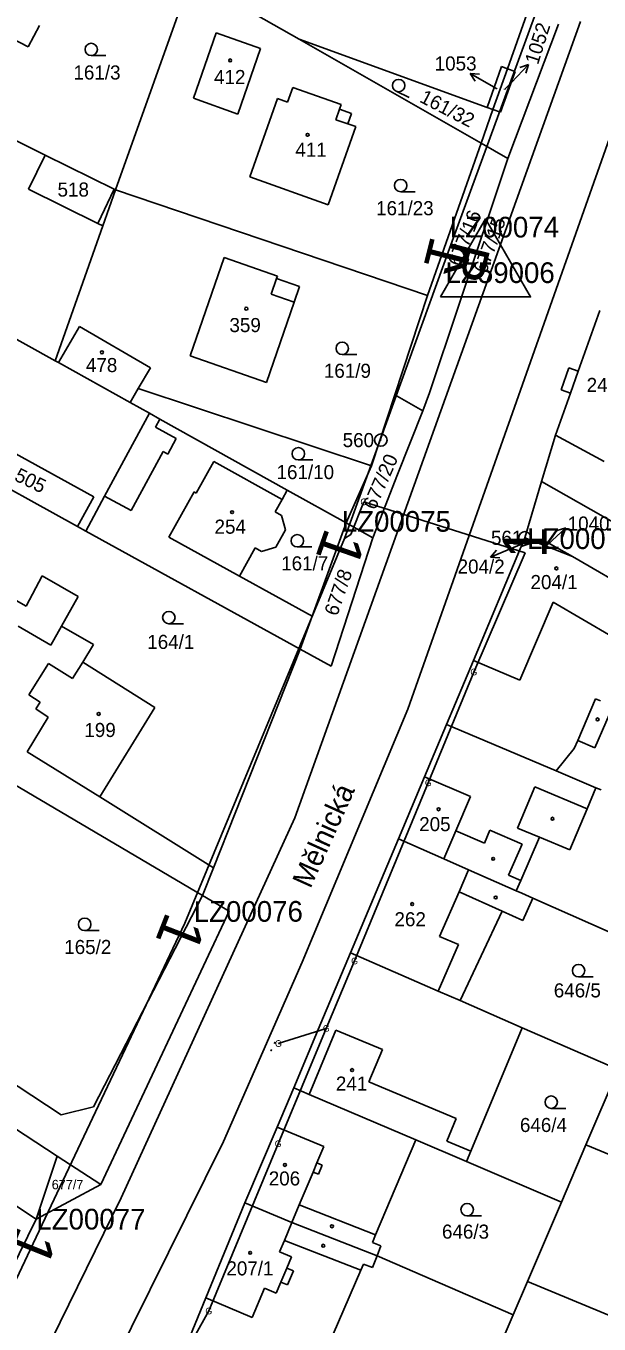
# Model space of a CAD drawing. Extents: x -738131 to -734179, y -1033447 to -1030078.
# Drawn here: x -736203.5 to -736134.3, y -1032598.8 to -1032442 of the extents above; entities that cross this region are included whole.
import ezdxf

# ---------------------------------------------------------------- set-up
doc = ezdxf.new("R2010")
doc.units = 0
for name, color, linetype in [('ftf_2010', 7, 'Continuous'), ('ftf_2050', 7, 'Continuous'), ('ftf_2240', 7, 'Continuous'), ('ftf_3010', 7, 'Continuous'), ('ftf_3010_ftf_3010_gtda_3015_gtda_3015_1', 7, 'Continuous'), ('ftf_3130', 7, 'Continuous'), ('ftf_3240', 7, 'Continuous'), ('ftf_3270', 7, 'Continuous'), ('ftf_3270_ftf_3270_gtda_3275_gtda_3275_1', 7, 'Continuous'), ('ftf_nu', 7, 'Continuous'), ('Vrstva 1', 7, 'Continuous'), ('Vrstva 2', 7, 'Continuous'), ('Vrstva 3', 7, 'Continuous'), ('Vrstva 4', 7, 'Continuous'), ('Vrstva 5', 7, 'Continuous'), ('Vrstva 7', 7, 'Continuous'), ('Vrstva 8', 7, 'Continuous')]:
    doc.layers.add(name, color=color, linetype=linetype)

msp = doc.modelspace()

# ---------------------------------------------------------------- linework, layer by layer
at = {"layer": 'ftf_2010'}
for points in [[(-736140.32, -1032436.02), (-736152.22, -1032468.46)], [(-736165.07, -1032503.95), (-736152.22, -1032468.46)], [(-736165.07, -1032503.95), (-736164.3, -1032503.44), (-736162.74, -1032499.51)], [(-736184.37, -1032550.41), (-736165.07, -1032503.95)], [(-736184.37, -1032550.41), (-736202.33, -1032588.35)], [(-736221.64, -1032629.17), (-736202.33, -1032588.35)]]:
    msp.add_lwpolyline(points, dxfattribs=at)
at = {"layer": 'ftf_2050'}
for points in [[(-736162.74, -1032499.51), (-736143.22, -1032505.69)], [(-736192.27, -1032616.69), (-736181.47, -1032597.25), (-736173.09, -1032577.05), (-736167.27, -1032563.11), (-736163.85, -1032554.97), (-736154.94, -1032533.45), (-736149.45, -1032520.07), (-736143.22, -1032505.69)], [(-736173.06, -1032564.94), (-736167.27, -1032563.11)]]:
    msp.add_lwpolyline(points, dxfattribs=at)
at = {"layer": 'ftf_2240'}
msp.add_lwpolyline([(-736153.46, -1032474.76), (-736142.58, -1032474.76), (-736148.02, -1032465.33)], close=True, dxfattribs=at)
at = {"layer": 'Vrstva 1'}
for points in [[(-736138.11, -1032426.67), (-736145.37, -1032447.19)], [(-736183.6, -1032436.18), (-736192.74, -1032461.81)], [(-736177.86, -1032439.46), (-736170.55, -1032443.63)], [(-736203.28, -1032444.56), (-736208.69, -1032441.76)], [(-736136.53, -1032441.5), (-736171.05, -1032537.69)], [(-736201.92, -1032441.96), (-736203.28, -1032444.56)], [(-736183.32, -1032450.77), (-736180.55, -1032442.88)], [(-736180.55, -1032442.88), (-736175.2, -1032444.76)], [(-736139.18, -1032441.8), (-736145.31, -1032458.03)], [(-736175.2, -1032444.76), (-736177.96, -1032452.67)], [(-736170.55, -1032443.63), (-736148.55, -1032456.18)], [(-736147.83, -1032451.86), (-736170.55, -1032443.63)], [(-736129.47, -1032445.45), (-736157.4, -1032524.54)], [(-736201.23, -1032457.62), (-736221.77, -1032447.35)], [(-736146.08, -1032446.94), (-736147.83, -1032451.86)], [(-736147.13, -1032452.11), (-736145.37, -1032447.19)], [(-736144.44, -1032447.52), (-736146.2, -1032452.44)], [(-736145.37, -1032447.19), (-736146.08, -1032446.94)], [(-736145.37, -1032447.19), (-736144.44, -1032447.52)], [(-736171.31, -1032449.45), (-736171.96, -1032451.25)], [(-736165.45, -1032451.52), (-736171.31, -1032449.45)], [(-736177.96, -1032452.67), (-736183.32, -1032450.77)], [(-736173.17, -1032450.81), (-736176.48, -1032460.24)], [(-736171.96, -1032451.25), (-736173.17, -1032450.81)], [(-736165.65, -1032452.1), (-736165.45, -1032451.52)], [(-736164.21, -1032452.61), (-736165.65, -1032452.1)], [(-736164.65, -1032453.86), (-736164.21, -1032452.61)], [(-736147.13, -1032452.11), (-736148.55, -1032456.18)], [(-736147.13, -1032452.11), (-736147.83, -1032451.86)], [(-736146.2, -1032452.44), (-736147.13, -1032452.11)], [(-736167.05, -1032463.62), (-736163.67, -1032454.18)], [(-736163.67, -1032454.18), (-736164.65, -1032453.86)], [(-736148.55, -1032456.18), (-736155.02, -1032474.6)], [(-736148.55, -1032456.18), (-736145.31, -1032458.03)], [(-736201.23, -1032457.62), (-736203.26, -1032461.74)], [(-736192.88, -1032461.74), (-736201.23, -1032457.62)], [(-736145.31, -1032458.03), (-736151.27, -1032475.87)], [(-736176.48, -1032460.24), (-736167.05, -1032463.62)], [(-736203.26, -1032461.74), (-736194.85, -1032465.88)], [(-736192.74, -1032461.81), (-736194.27, -1032466.16)], [(-736192.74, -1032461.81), (-736192.88, -1032461.74)], [(-736155.02, -1032474.6), (-736192.74, -1032461.81)], [(-736200.01, -1032482.48), (-736230.49, -1032465.51)], [(-736194.27, -1032466.16), (-736200.01, -1032482.48)], [(-736194.85, -1032465.88), (-736194.27, -1032466.16)], [(-736183.72, -1032481.89), (-736179.58, -1032470.01)], [(-736179.58, -1032470.01), (-736173.16, -1032472.25)], [(-736173.16, -1032472.25), (-736173.26, -1032472.53)], [(-736170.48, -1032473.49), (-736173.26, -1032472.53)], [(-736171.13, -1032475.38), (-736170.48, -1032473.49)], [(-736158.98, -1032486.59), (-736155.02, -1032474.6)], [(-736171.13, -1032475.38), (-736174.49, -1032485.11)], [(-736151.27, -1032475.87), (-736154.77, -1032486.36)], [(-736134.21, -1032476.39), (-736136.82, -1032483.74)], [(-736197.09, -1032478.34), (-736199.62, -1032482.7)], [(-736188.5, -1032483.33), (-736197.09, -1032478.34)], [(-736200.01, -1032482.48), (-736199.62, -1032482.7)], [(-736174.49, -1032485.11), (-736183.72, -1032481.89)], [(-736199.62, -1032482.7), (-736190.97, -1032487.52)], [(-736189.97, -1032485.82), (-736188.5, -1032483.33)], [(-736137.95, -1032483.34), (-736138.89, -1032485.98)], [(-736136.82, -1032483.74), (-736137.95, -1032483.34)], [(-736190.97, -1032487.52), (-736189.97, -1032485.82)], [(-736189.97, -1032485.82), (-736161.81, -1032495.17)], [(-736161.81, -1032495.17), (-736158.98, -1032486.59)], [(-736158.98, -1032486.59), (-736155.61, -1032488.51)], [(-736155.61, -1032488.51), (-736154.77, -1032486.36)], [(-736137.76, -1032486.38), (-736139.57, -1032491.47)], [(-736138.89, -1032485.98), (-736137.76, -1032486.38)], [(-736190.97, -1032487.52), (-736188.62, -1032488.82)], [(-736158.64, -1032496.22), (-736155.61, -1032488.51)], [(-736188.62, -1032488.82), (-736194.05, -1032498.84)], [(-736188.62, -1032488.82), (-736187.36, -1032489.53)], [(-736187.36, -1032489.53), (-736171.97, -1032498.1)], [(-736209.21, -1032491.28), (-736195.34, -1032498.92)], [(-736141.24, -1032497.07), (-736139.57, -1032491.47)], [(-736133.68, -1032494.64), (-736139.57, -1032491.47)], [(-736197.31, -1032502.49), (-736211.18, -1032494.85)], [(-736164.86, -1032502.06), (-736161.81, -1032495.17)], [(-736161.63, -1032503.86), (-736158.64, -1032496.22)], [(-736171.97, -1032498.1), (-736172.6, -1032499.23)], [(-736171.97, -1032498.1), (-736164.86, -1032502.06)], [(-736143.26, -1032503.85), (-736141.24, -1032497.07)], [(-736141.24, -1032497.07), (-736107.27, -1032516.33)], [(-736195.34, -1032498.92), (-736197.31, -1032502.49)], [(-736196.32, -1032503.04), (-736194.05, -1032498.84)], [(-736172.6, -1032499.23), (-736173.43, -1032500.71)], [(-736173.43, -1032500.71), (-736172.65, -1032501.15)], [(-736172.65, -1032501.15), (-736172.19, -1032502.89)], [(-736197.31, -1032502.49), (-736196.32, -1032503.04)], [(-736172.19, -1032502.89), (-736173.36, -1032504.99)], [(-736164.86, -1032502.06), (-736168.97, -1032513.32)], [(-736164.86, -1032502.06), (-736161.63, -1032503.86)], [(-736196.32, -1032503.04), (-736170.42, -1032517.31)], [(-736166.66, -1032519.38), (-736161.63, -1032503.86)], [(-736143.71, -1032504.91), (-736143.26, -1032503.85)], [(-736143.71, -1032504.91), (-736142.03, -1032504.34)], [(-736143.26, -1032503.85), (-736142.03, -1032504.34)], [(-736142.03, -1032504.34), (-736141.19, -1032504.05)], [(-736142.03, -1032504.34), (-736137.49, -1032506.13)], [(-736137.49, -1032506.13), (-736141.19, -1032504.05)], [(-736177.76, -1032508.47), (-736175.86, -1032505.07)], [(-736175.08, -1032505.51), (-736175.86, -1032505.07)], [(-736173.36, -1032504.99), (-736175.08, -1032505.51)], [(-736149.47, -1032518.66), (-736143.71, -1032504.91)], [(-736129.73, -1032510.63), (-736137.49, -1032506.13)], [(-736209.99, -1032508.46), (-736203.54, -1032512.11)], [(-736203.54, -1032512.11), (-736201.57, -1032508.46)], [(-736201.57, -1032508.46), (-736197.24, -1032510.94)], [(-736168.97, -1032513.32), (-736177.76, -1032508.47)], [(-736197.24, -1032510.94), (-736199.25, -1032514.54)], [(-736170.42, -1032517.31), (-736168.97, -1032513.32)], [(-736199.25, -1032514.54), (-736195.38, -1032516.74)], [(-736195.38, -1032516.74), (-736196.69, -1032518.87)], [(-736170.42, -1032517.31), (-736180.88, -1032543.74)], [(-736170.42, -1032517.31), (-736166.66, -1032519.38)], [(-736196.69, -1032518.87), (-736187.98, -1032524.34)], [(-736149.47, -1032518.66), (-736152.73, -1032526.39)], [(-736134.79, -1032529.22), (-736132.16, -1032523.12)], [(-736187.98, -1032524.34), (-736194.62, -1032535.14)], [(-736157.4, -1032524.54), (-736170.16, -1032555.11)], [(-736152.73, -1032526.39), (-736155.39, -1032532.73)], [(-736152.73, -1032526.39), (-736139.48, -1032532.01)], [(-736139.48, -1032532.01), (-736137.31, -1032529.32)], [(-736137.31, -1032529.32), (-736136.88, -1032528.32)], [(-736134.79, -1032529.22), (-736136.88, -1032528.32)], [(-736139.48, -1032532.01), (-736134.7, -1032534.04)], [(-736205.03, -1032533.62), (-736182.2, -1032547.07)], [(-736155.39, -1032532.73), (-736158.54, -1032540.21)], [(-736135.75, -1032536.58), (-736134.7, -1032534.04)], [(-736134.7, -1032534.04), (-736134.06, -1032534.31)], [(-736180.88, -1032543.74), (-736194.62, -1032535.14)], [(-736137.82, -1032541.56), (-736135.75, -1032536.58)], [(-736171.05, -1032537.69), (-736192.06, -1032583.58)], [(-736158.54, -1032540.21), (-736161.23, -1032546.62)], [(-736158.54, -1032540.21), (-736153.04, -1032542.64)], [(-736143.76, -1032545.25), (-736141.51, -1032540.02)], [(-736141.51, -1032540.02), (-736137.82, -1032541.56)], [(-736153.04, -1032542.64), (-736150.06, -1032543.96)], [(-736182.2, -1032547.07), (-736180.88, -1032543.74)], [(-736144.3, -1032546.5), (-736150.06, -1032543.96)], [(-736161.23, -1032546.62), (-736164.33, -1032553.99)], [(-736144.3, -1032546.5), (-736143.76, -1032545.25)], [(-736143.64, -1032546.79), (-736144.3, -1032546.5)], [(-736142.3, -1032547.39), (-736143.64, -1032546.79)], [(-736182.2, -1032547.07), (-736195.37, -1032572.58)], [(-736182.2, -1032547.07), (-736179, -1032548.95)], [(-736142.3, -1032547.39), (-736143.52, -1032550.09)], [(-736142.3, -1032547.39), (-736126.18, -1032554.51)], [(-736194.49, -1032581.99), (-736179, -1032548.95)], [(-736146.01, -1032548.97), (-736151.07, -1032559.76)], [(-736143.52, -1032550.09), (-736146.01, -1032548.97)], [(-736164.33, -1032553.99), (-736167.91, -1032562.5)], [(-736164.33, -1032553.99), (-736153.75, -1032558.6)], [(-736170.16, -1032555.11), (-736179.69, -1032576.78)], [(-736199.28, -1032573.57), (-736225.57, -1032556.27)], [(-736151.07, -1032559.76), (-736153.75, -1032558.6)], [(-736228.16, -1032559.94), (-736199.76, -1032578.54)], [(-736143.57, -1032563.03), (-736151.07, -1032559.76)], [(-736167.91, -1032562.5), (-736171.19, -1032570.3)], [(-736143.57, -1032563.03), (-736149.78, -1032577.96)], [(-736131.98, -1032568.07), (-736143.57, -1032563.03)], [(-736131.98, -1032568.07), (-736135.88, -1032577.19)], [(-736171.19, -1032570.3), (-736173.18, -1032575.05)], [(-736169.34, -1032571.09), (-736171.19, -1032570.3)], [(-736156.45, -1032576.59), (-736169.34, -1032571.09)], [(-736199.28, -1032573.57), (-736195.37, -1032572.58)], [(-736177.11, -1032584.18), (-736173.18, -1032575.05)], [(-736161.32, -1032588.03), (-736156.45, -1032576.59)], [(-736150.3, -1032579.21), (-736156.45, -1032576.59)], [(-736214.51, -1032578.06), (-736202.32, -1032586.14)], [(-736179.69, -1032576.78), (-736197.43, -1032612.62)], [(-736149.78, -1032577.96), (-736150.3, -1032579.21)], [(-736135.88, -1032577.19), (-736138.84, -1032584.1)], [(-736135.88, -1032577.19), (-736108.36, -1032588.58)], [(-736202.32, -1032586.14), (-736199.76, -1032578.54)], [(-736199.76, -1032578.54), (-736194.49, -1032581.99)], [(-736138.84, -1032584.1), (-736150.3, -1032579.21)], [(-736202.32, -1032586.14), (-736194.49, -1032581.99)], [(-736192.06, -1032583.58), (-736209.97, -1032620)], [(-736177.11, -1032584.18), (-736181.81, -1032595.67)], [(-736171.41, -1032586.56), (-736177.11, -1032584.18)], [(-736138.84, -1032584.1), (-736142.94, -1032593.68)], [(-736202.32, -1032586.14), (-736214.65, -1032611.21)], [(-736161.13, -1032590.58), (-736171.41, -1032586.56)], [(-736161.32, -1032588.03), (-736161.69, -1032588.96)], [(-736161.69, -1032588.96), (-736160.66, -1032589.37)], [(-736161.13, -1032590.58), (-736161.69, -1032592.01)], [(-736160.66, -1032589.37), (-736161.13, -1032590.58)], [(-736161.13, -1032590.58), (-736144.67, -1032597.7)], [(-736162.78, -1032591.58), (-736163.07, -1032592.33)], [(-736161.69, -1032592.01), (-736162.78, -1032591.58)], [(-736163.07, -1032592.33), (-736167.83, -1032603.32)], [(-736142.94, -1032593.68), (-736144.67, -1032597.7)], [(-736113.43, -1032605.92), (-736142.94, -1032593.68)], [(-736181.81, -1032595.67), (-736183.74, -1032600.39)], [(-736150.39, -1032611.09), (-736144.67, -1032597.7)]]:
    msp.add_lwpolyline(points, dxfattribs=at)
at = {"layer": 'Vrstva 3'}
for p, q in [((-736195.66, -1032445.61), (-736193.91, -1032445.61)), ((-736158.83, -1032449.91), (-736157.25, -1032450.66)), ((-736158.27, -1032462.06), (-736156.52, -1032462.06)), ((-736165.33, -1032481.72), (-736163.58, -1032481.72)), ((-736170.63, -1032494.45), (-736168.88, -1032494.45)), ((-736170.76, -1032504.96), (-736169.01, -1032504.96)), ((-736186.28, -1032514.24), (-736184.53, -1032514.24)), ((-736196.45, -1032551.3), (-736194.7, -1032551.3)), ((-736136.77, -1032556.89), (-736135.02, -1032556.89)), ((-736140.08, -1032572.77), (-736138.33, -1032572.77)), ((-736150.24, -1032585.76), (-736148.49, -1032585.76))]:
    msp.add_line(p, q, dxfattribs=at)
for centre in [(-736195.66, -1032444.86), (-736158.51, -1032449.23), (-736158.27, -1032461.31), (-736165.33, -1032480.97), (-736170.63, -1032493.7), (-736170.76, -1032504.21), (-736186.28, -1032513.49), (-736196.45, -1032550.55), (-736136.77, -1032556.14), (-736140.08, -1032572.02), (-736150.24, -1032585.01)]:
    msp.add_circle(centre, 0.75, dxfattribs=at)
at = {"layer": 'Vrstva 4'}
for points in [[(-736165.65, -1032452.1), (-736166.09, -1032453.35)], [(-736166.09, -1032453.35), (-736164.65, -1032453.86)], [(-736192.88, -1032461.74), (-736194.85, -1032465.88)], [(-736173.26, -1032472.53), (-736173.91, -1032474.41)], [(-736173.91, -1032474.41), (-736171.13, -1032475.38)], [(-736137.76, -1032486.38), (-736136.82, -1032483.74)], [(-736187.36, -1032489.53), (-736187.89, -1032490.51)], [(-736187.89, -1032490.51), (-736185.39, -1032491.86)], [(-736185.39, -1032491.86), (-736186.4, -1032493.74)], [(-736186.98, -1032493.43), (-736190.83, -1032500.57)], [(-736186.4, -1032493.74), (-736186.98, -1032493.43)], [(-736182.98, -1032498.47), (-736180.84, -1032494.64)], [(-736180.84, -1032494.64), (-736172.6, -1032499.23)], [(-736190.83, -1032500.57), (-736194.05, -1032498.84)], [(-736186.28, -1032503.77), (-736183.24, -1032498.32)], [(-736183.24, -1032498.32), (-736182.98, -1032498.47)], [(-736177.76, -1032508.47), (-736186.28, -1032503.77)], [(-736143.87, -1032521.05), (-736139.84, -1032511.63)], [(-736139.84, -1032511.63), (-736132.67, -1032515.81)], [(-736204.49, -1032514.53), (-736200.53, -1032516.83)], [(-736200.53, -1032516.83), (-736199.25, -1032514.54)], [(-736200.82, -1032519.02), (-736203.2, -1032522.81)], [(-736197.91, -1032520.85), (-736200.82, -1032519.02)], [(-736196.69, -1032518.87), (-736197.91, -1032520.85)], [(-736149.47, -1032518.66), (-736143.87, -1032521.05)], [(-736203.2, -1032522.81), (-736201.82, -1032523.71)], [(-736201.82, -1032523.71), (-736202.35, -1032524.53)], [(-736202.35, -1032524.53), (-736200.85, -1032525.54)], [(-736136.88, -1032528.32), (-736134.73, -1032523.31)], [(-736134.73, -1032523.31), (-736134.13, -1032523.56)], [(-736200.85, -1032525.54), (-736203.4, -1032529.72)], [(-736203.4, -1032529.72), (-736194.62, -1032535.14)], [(-736149.82, -1032535.11), (-736155.39, -1032532.73)], [(-736142.07, -1032533.95), (-736144.14, -1032538.93)], [(-736135.75, -1032536.58), (-736142.07, -1032533.95)], [(-736149.82, -1032535.11), (-736151.6, -1032539.27)], [(-736144.14, -1032538.93), (-736141.51, -1032540.02)], [(-736151.6, -1032539.27), (-736153.04, -1032542.64)], [(-736151.6, -1032539.27), (-736148.15, -1032540.74)], [(-736148.15, -1032540.74), (-736147.48, -1032539.18)], [(-736147.48, -1032539.18), (-736143.57, -1032540.85)], [(-736145.23, -1032544.6), (-736143.57, -1032540.85)], [(-736150.06, -1032543.96), (-736151.22, -1032546.62)], [(-736145.23, -1032544.6), (-736143.76, -1032545.25)], [(-736151.22, -1032546.62), (-736153.57, -1032552)], [(-736146.01, -1032548.97), (-736151.22, -1032546.62)], [(-736151.3, -1032552.99), (-736153.75, -1032558.6)], [(-736153.57, -1032552), (-736151.3, -1032552.99)], [(-736166.09, -1032563.33), (-736169.34, -1032571.09)], [(-736160.48, -1032565.68), (-736166.09, -1032563.33)], [(-736162.11, -1032569.57), (-736160.48, -1032565.68)], [(-736151.55, -1032574), (-736162.11, -1032569.57)], [(-736152.69, -1032576.74), (-736151.55, -1032574)], [(-736173.18, -1032575.05), (-736167.56, -1032577.39)], [(-736167.56, -1032577.39), (-736168.39, -1032579.36)], [(-736149.78, -1032577.96), (-736152.69, -1032576.74)], [(-736168.39, -1032579.36), (-736168.85, -1032580.47)], [(-736168.39, -1032579.36), (-736167.74, -1032579.64)], [(-736167.74, -1032579.64), (-736168.21, -1032580.74)], [(-736168.85, -1032580.47), (-736170.52, -1032584.44)], [(-736168.21, -1032580.74), (-736168.85, -1032580.47)], [(-736170.52, -1032584.44), (-736171.41, -1032586.56)], [(-736170.52, -1032584.44), (-736161.32, -1032588.03)], [(-736172.32, -1032588.72), (-736171.41, -1032586.56)], [(-736172.9, -1032590.09), (-736172.32, -1032588.72)], [(-736163.07, -1032592.33), (-736172.32, -1032588.72)], [(-736172.9, -1032590.09), (-736171.45, -1032590.7)], [(-736171.45, -1032590.7), (-736172.03, -1032592.06)], [(-736172.74, -1032593.75), (-736172.03, -1032592.06)], [(-736172.03, -1032592.06), (-736171.23, -1032592.39)], [(-736172.74, -1032593.75), (-736173.31, -1032595.09)], [(-736171.95, -1032594.09), (-736172.74, -1032593.75)], [(-736171.23, -1032592.39), (-736171.95, -1032594.09)], [(-736174.73, -1032594.49), (-736176.22, -1032598.02)], [(-736173.31, -1032595.09), (-736174.73, -1032594.49)], [(-736181.81, -1032595.67), (-736176.22, -1032598.02)]]:
    msp.add_lwpolyline(points, dxfattribs=at)
at = {"layer": 'Vrstva 5'}
for centre in [(-736178.87, -1032446.19), (-736169.51, -1032455.18), (-736176.92, -1032476.18), (-736194.37, -1032481.45), (-736178.64, -1032500.76), (-736143.05, -1032504.3), (-736139.46, -1032507.55), (-736194.76, -1032525.13), (-736134.48, -1032525.79), (-736153.69, -1032536.64), (-736139.93, -1032537.79), (-736147.1, -1032542.63), (-736156.88, -1032548.1), (-736146.79, -1032547.3), (-736164.14, -1032568.15), (-736172.25, -1032579.61), (-736166.57, -1032587.02), (-736176.46, -1032590.22), (-736167.62, -1032589.37)]:
    msp.add_circle(centre, 0.175, dxfattribs=at)
at = {"layer": 'Vrstva 7'}
for p, q in [((-736147.27, -1032449.28), (-736149.87, -1032447.78)), ((-736149.87, -1032447.78), (-736148.75, -1032447.85)), ((-736149.87, -1032447.78), (-736149.25, -1032448.71)), ((-736144.89, -1032448.84), (-736142.82, -1032446.67)), ((-736142.82, -1032446.67), (-736143.87, -1032447.05)), ((-736142.82, -1032446.67), (-736143.15, -1032447.73)), ((-736140.52, -1032504.69), (-736138.3, -1032502.67)), ((-736138.3, -1032502.67), (-736139.37, -1032502.97)), ((-736138.3, -1032502.67), (-736138.7, -1032503.72)), ((-736144.65, -1032505.04), (-736147.41, -1032506.21)), ((-736147.41, -1032506.21), (-736146.69, -1032505.36)), ((-736147.41, -1032506.21), (-736146.3, -1032506.28))]:
    msp.add_line(p, q, dxfattribs=at)
for points in [[(-736146.66, -1032449.63), (-736147.27, -1032449.28)], [(-736145.71, -1032449.71), (-736144.89, -1032448.84)], [(-736142.98, -1032504.33), (-736144.65, -1032505.04)], [(-736140.56, -1032504.72), (-736140.52, -1032504.69)]]:
    msp.add_lwpolyline(points, dxfattribs=at)
at = {"layer": 'Vrstva 8'}
for centre, radius in [((-736160.67, -1032492.05), 0.75), ((-736160.67, -1032492.05), 0.03), ((-736143.26, -1032503.85), 0.75), ((-736143.26, -1032503.85), 0.03)]:
    msp.add_circle(centre, radius, dxfattribs=at)

# ---------------------------------------------------------------- texts
at = {"layer": 'ftf_3010'}
for rotation, p in [(255.9575, (-736154.59, -1032467.2)), (90, (-736140.62, -1032506.34)), (250.7016, (-736167.31, -1032502.48)), (248.7063, (-736186.55, -1032548.86)), (248.1856, (-736204.5, -1032586.78))]:
    msp.add_text('1', height=5.2, rotation=rotation, dxfattribs=at).set_placement(p)
at = {"layer": 'ftf_3010_ftf_3010_gtda_3015_gtda_3015_1'}
for s, rotation, p in [('LZ00074', 0, (-736152.33, -1032467.58)), ('LZ00075', 0, (-736165.39, -1032503.12)), ('LZ00071', 0, (-736142.98, -1032505.21)), ('LZ00076', 0.1236, (-736183.28, -1032550.25)), ('LZ00077', 0, (-736202.3, -1032587.41))]:
    msp.add_text(s, height=2.5, rotation=rotation, dxfattribs=at).set_placement(p)
at = {"layer": 'ftf_3130'}
msp.add_text(':', height=1.6, rotation=335.1094, dxfattribs=at).set_placement((-736174.23, -1032565.74))
at = {"layer": 'ftf_3240'}
for p in [(-736163.14, -1032499.91), (-736149.85, -1032520.47), (-736155.34, -1032533.85), (-736164.25, -1032555.37), (-736167.67, -1032563.51), (-736173.46, -1032565.34), (-736173.49, -1032577.45), (-736181.87, -1032597.65)]:
    msp.add_text('G', height=0.8, dxfattribs=at).set_placement(p)
at = {"layer": 'ftf_3270'}
msp.add_text('R', height=4.8, rotation=255.8093, dxfattribs=at).set_placement((-736152.05, -1032467.78))
at = {"layer": 'ftf_3270_ftf_3270_gtda_3275_gtda_3275_1'}
msp.add_text('LZ59006', height=2.5, rotation=0, dxfattribs=at).set_placement((-736152.85, -1032473.08))
at = {"layer": 'ftf_nu'}
msp.add_text('Mělnická', height=2.5, rotation=65.7521, dxfattribs=at).set_placement((-736169.18, -1032546.32))
at = {"layer": 'Vrstva 2'}
for s, height, p in [('161/3', 1.7, (-736197.81, -1032448.5)), ('412', 1.7, (-736180.82, -1032449.05)), ('1053', 0.1, (-736146.8, -1032449.63)), ('1052', 0.1, (-736145.85, -1032449.71)), ('411', 1.7, (-736171, -1032457.83)), ('518', 1.7, (-736199.73, -1032462.64)), ('161/23', 1.7, (-736161.24, -1032464.89)), ('359', 1.7, (-736178.96, -1032479.01)), ('478', 1.7, (-736196.3, -1032483.84)), ('161/9', 1.7, (-736167.55, -1032484.53)), ('246', 1.7, (-736135.8, -1032486.24)), ('161/10', 1.7, (-736173.27, -1032496.77)), ('254', 1.7, (-736180.76, -1032503.36)), ('204/2', 0.1, (-736143.17, -1032504.33)), ('161/7', 1.7, (-736172.71, -1032507.79)), ('1040', 0.1, (-736140.68, -1032504.72)), ('204/1', 1.7, (-736142.58, -1032510.05)), ('164/1', 1.7, (-736188.89, -1032517.28)), ('199', 1.7, (-736196.49, -1032527.92)), ('205', 1.7, (-736156.03, -1032539.29)), ('262', 1.7, (-736159.02, -1032550.78)), ('165/2', 1.7, (-736198.92, -1032554.13)), ('646/5', 1.7, (-736139.77, -1032559.37)), ('241', 1.7, (-736166.1, -1032570.63)), ('646/4', 1.7, (-736143.86, -1032575.63)), ('206', 1.7, (-736174.21, -1032582.09)), ('677/7', 1.14, (-736200.43, -1032582.55)), ('646/3', 1.7, (-736153.28, -1032588.51)), ('207/1', 1.7, (-736179.33, -1032592.95))]:
    msp.add_text(s, height=height, dxfattribs=at).set_placement(p)
for s, rotation, p in [('161/32', 332.6403, (-736156.1, -1032451.15)), ('677/16', 68.1986, (-736151.07, -1032471.18)), ('677/15', 69.5926, (-736147.95, -1032472.03)), ('677/20', 66.1891, (-736161.34, -1032500.59)), ('505', 334.1869, (-736205.07, -1032496.87)), ('677/8', 71.0355, (-736165.94, -1032513.4))]:
    msp.add_text(s, height=1.7, rotation=rotation, dxfattribs=at).set_placement(p)
at = {"layer": 'Vrstva 7'}
msp.add_text('1052', height=1.7, rotation=72.456, dxfattribs=at).set_placement((-736141.68, -1032446.79))
for s, p in [('1053', (-736154.16, -1032447.41)), ('1040', (-736138.09, -1032502.98)), ('204/2', (-736151.39, -1032508.18))]:
    msp.add_text(s, height=1.7, dxfattribs=at).set_placement(p)
at = {"layer": 'Vrstva 8'}
for s, p in [('560', (-736165.28, -1032492.9)), ('561', (-736147.36, -1032504.7))]:
    msp.add_text(s, height=1.7, dxfattribs=at).set_placement(p)

doc.saveas('drawing.dxf')
